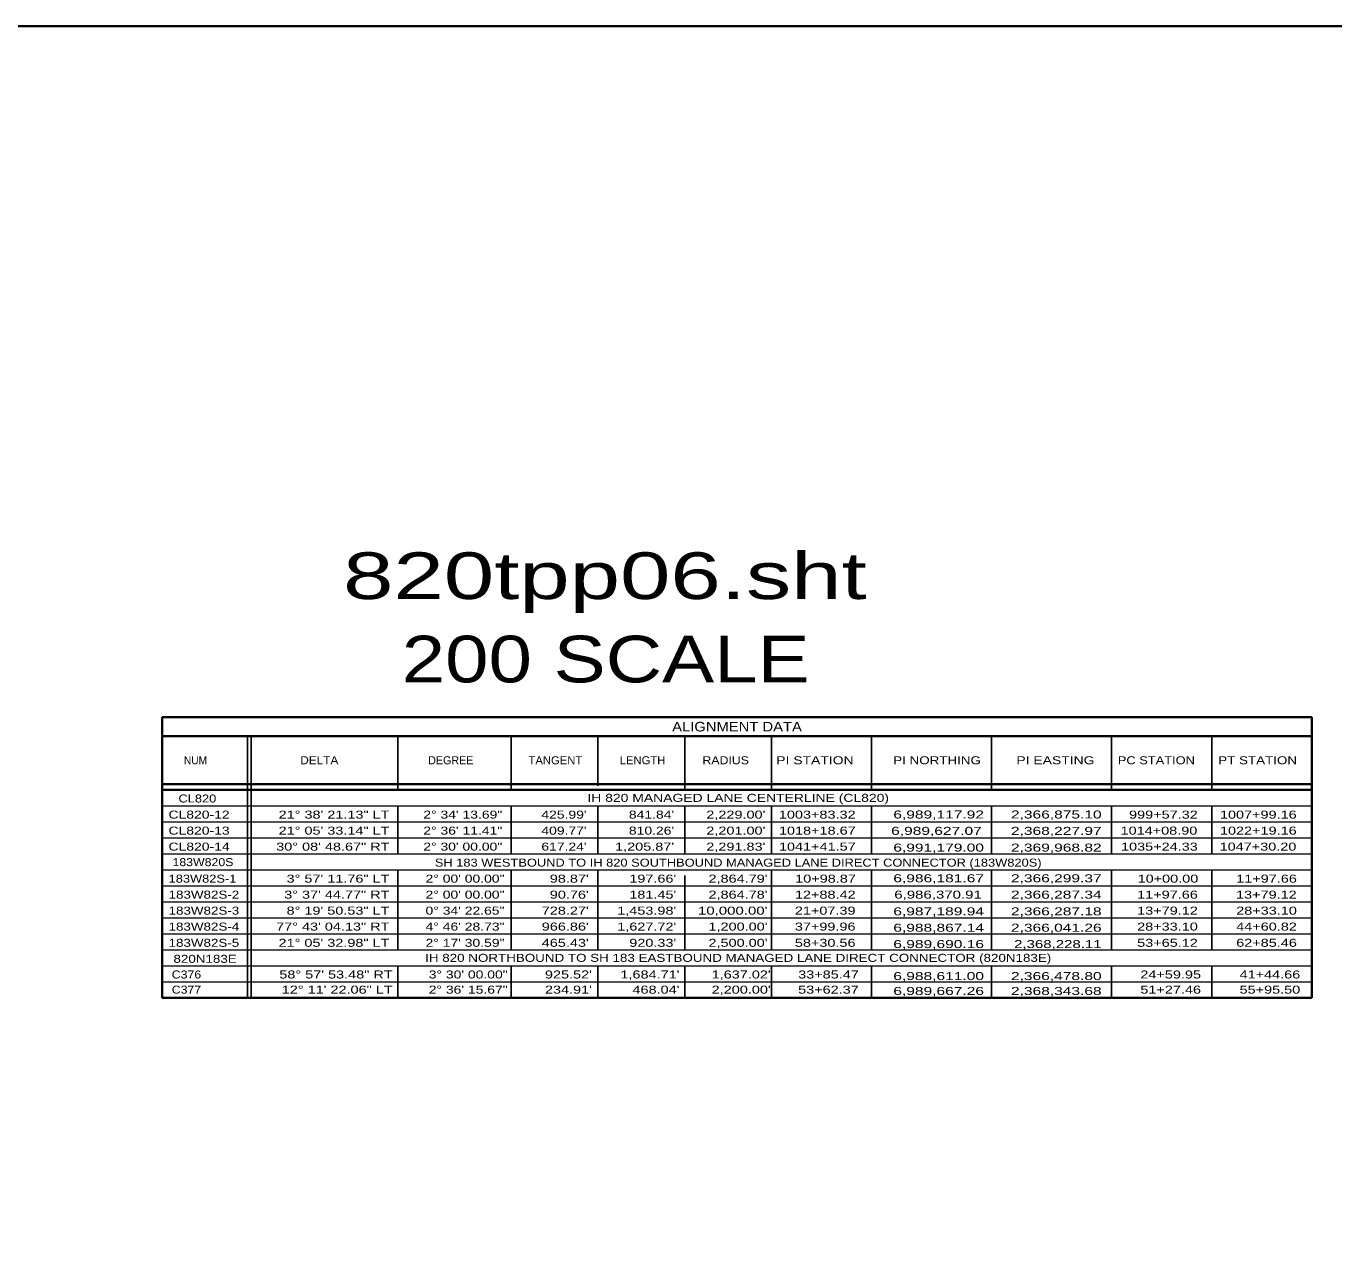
# Model space of a CAD drawing. Extents: x 1953053 to 1967065, y 7363860 to 7371201.
# Drawn here: x 1963762 to 1965722, y 7369366 to 7371201 of the extents above; entities that cross this region are included whole.
import ezdxf
from ezdxf.enums import TextEntityAlignment as Align

# ---------------------------------------------------------------- set-up
doc = ezdxf.new("R2010")
doc.units = 0
doc.header["$LTSCALE"] = 4.8
doc.layers.add('10', color=7, linetype='Continuous')
doc.layers.add('12', color=7, linetype='Continuous', lineweight=25)
doc.layers.add('62', color=7, linetype='Continuous', lineweight=35)

msp = doc.modelspace()

# ---------------------------------------------------------------- linework, layer by layer
at = {"layer": '12', "lineweight": 35}
for p, q in [((1965689.378, 7370164.879), (1963966.046, 7370164.879)), ((1963966.046, 7370164.879), (1963966.046, 7369743.746)), ((1965689.378, 7369743.746), (1965689.378, 7370164.879)), ((1963966.046, 7370136.079), (1965689.378, 7370136.079)), ((1963966.046, 7370064.079), (1965689.378, 7370064.079)), ((1963966.046, 7370055.746), (1965689.378, 7370055.746)), ((1963966.046, 7369743.746), (1965689.378, 7369743.746))]:
    msp.add_line(p, q, dxfattribs=at)
at = {"layer": '12'}
for p, q in [((1964093.891, 7370136.079), (1964093.891, 7369743.746)), ((1964099.378, 7370136.079), (1964099.378, 7369743.746)), ((1964319.378, 7370136.079), (1964319.378, 7370055.746)), ((1964489.378, 7370136.079), (1964489.378, 7370055.746)), ((1964619.378, 7370136.079), (1964619.378, 7370061.892)), ((1964749.378, 7370136.079), (1964749.378, 7370055.746)), ((1964879.378, 7370136.079), (1964879.378, 7370055.746)), ((1965029.378, 7370136.079), (1965029.378, 7370055.746)), ((1965209.378, 7370136.079), (1965209.378, 7370055.746)), ((1965389.378, 7370136.079), (1965389.378, 7370056.955)), ((1965539.378, 7370136.079), (1965539.378, 7370055.746)), ((1964093.891, 7370114.479), (1964093.891, 7369838.526)), ((1964319.378, 7370031.746), (1964319.378, 7369959.746)), ((1964489.378, 7370031.746), (1964489.378, 7369959.746)), ((1964619.378, 7370031.746), (1964619.378, 7369959.746)), ((1964749.378, 7370031.746), (1964749.378, 7369959.746)), ((1964879.378, 7370031.746), (1964879.378, 7369959.746)), ((1965029.378, 7370031.746), (1965029.378, 7369959.746)), ((1965209.378, 7370031.746), (1965209.378, 7369959.746)), ((1965389.378, 7370031.746), (1965389.378, 7369959.746)), ((1965539.378, 7370031.746), (1965539.378, 7369959.746)), ((1964319.378, 7369935.746), (1964319.378, 7369815.746)), ((1964489.378, 7369935.746), (1964489.378, 7369815.746)), ((1964619.378, 7369935.746), (1964619.378, 7369815.746)), ((1964749.378, 7369927.372), (1964749.378, 7369815.746)), ((1964879.378, 7369935.746), (1964879.378, 7369815.746)), ((1965029.378, 7369935.746), (1965029.378, 7369815.746)), ((1965209.378, 7369935.746), (1965209.378, 7369815.746)), ((1965389.378, 7369935.746), (1965389.378, 7369815.746)), ((1965539.378, 7369935.746), (1965539.378, 7369815.746)), ((1964319.378, 7369791.746), (1964319.378, 7369743.746)), ((1964489.378, 7369791.746), (1964489.378, 7369743.746)), ((1964619.378, 7369791.746), (1964619.378, 7369743.746)), ((1964749.378, 7369791.746), (1964749.378, 7369743.746)), ((1964879.378, 7369791.746), (1964879.378, 7369743.746)), ((1965029.378, 7369791.746), (1965029.378, 7369743.746)), ((1965209.378, 7369791.746), (1965209.378, 7369743.746)), ((1965389.378, 7369791.746), (1965389.378, 7369743.746)), ((1965539.378, 7369791.746), (1965539.378, 7369743.746))]:
    msp.add_line(p, q, dxfattribs=at)
at = {"layer": '12', "lineweight": 13}
for p, q in [((1963966.046, 7370031.746), (1965689.378, 7370031.746)), ((1963966.046, 7370007.746), (1965689.378, 7370007.746)), ((1963966.046, 7369983.746), (1965689.378, 7369983.746)), ((1963966.046, 7369959.746), (1965689.378, 7369959.746)), ((1963966.046, 7369935.746), (1965689.378, 7369935.746)), ((1963966.046, 7369911.746), (1965689.378, 7369911.746)), ((1963966.046, 7369887.746), (1965689.378, 7369887.746)), ((1963966.046, 7369863.746), (1965689.378, 7369863.746)), ((1963966.046, 7369839.746), (1965689.378, 7369839.746)), ((1963966.046, 7369815.746), (1965689.378, 7369815.746)), ((1963966.046, 7369791.746), (1965689.378, 7369791.746)), ((1963966.046, 7369767.746), (1965689.378, 7369767.746))]:
    msp.add_line(p, q, dxfattribs=at)
at = {"layer": '62'}
msp.add_lwpolyline([(1953052.784, 7371201.108), (1967065.314, 7371201.108), (1967065.314, 7363859.877), (1953052.784, 7363859.877)], close=True, dxfattribs=at)

# ---------------------------------------------------------------- texts
at = {"layer": '10'}
for s, width, p in [('CL820', 1.2, (1963990.551, 7370036.747)), ('CL820-12', 1.3, (1963975.667, 7370012.572)), ('CL820-13', 1.3, (1963975.667, 7369988.572)), ('CL820-14', 1.3, (1963975.667, 7369964.572)), ('183W820S', 1.15, (1963981.635, 7369941.279)), ('183W82S-1', 1.2, (1963975.75, 7369916.572)), ('183W82S-2', 1.25, (1963975.75, 7369892.572)), ('183W82S-3', 1.25, (1963975.75, 7369868.572)), ('183W82S-4', 1.25, (1963975.75, 7369844.644)), ('183W82S-5', 1.25, (1963975.75, 7369820.31)), ('820N183E', 1.25, (1963983.108, 7369796.285)), ('C376', 1.15, (1963980.523, 7369772.787)), ('C377', 1.15, (1963980.523, 7369750.075))]:
    msp.add_text(s, height=12, dxfattribs=dict(at, width=width)).set_placement(p)
for s, width, p in [('IH 820 MANAGED LANE CENTERLINE (CL820)', 1.3, (1964829.576, 7370037.713)), ('SH 183 WESTBOUND TO IH 820 SOUTHBOUND MANAGED LANE DIRECT CONNECTOR (183W820S)', 1.2, (1964829.578, 7369940.563)), ('IH 820 NORTHBOUND TO SH 183 EASTBOUND MANAGED LANE DIRECT CONNECTOR (820N183E)', 1.25, (1964829.578, 7369797.757))]:
    msp.add_text(s, height=12, dxfattribs=dict(at, width=width)).set_placement(p, align=Align.CENTER)
for s, width, p in [('21° 38\' 21.13" LT', 1.35, (1964306.9, 7370012.572)), ('2° 34\' 13.69"', 1.3, (1964475.895, 7370012.572)), ("425.99'", 1.3, (1964602.305, 7370012.572)), ("841.84'", 1.3, (1964733.502, 7370012.572)), ("2,229.00'", 1.35, (1964870.272, 7370012.572)), ('1003+83.32', 1.35, (1965005.578, 7370012.572)), ('6,989,117.92', 1.45, (1965197.965, 7370012.75)), ('2,366,875.10', 1.45, (1965374.312, 7370012.75)), ('999+57.32', 1.35, (1965518.44, 7370012.572)), ('1007+99.16', 1.35, (1965666.701, 7370012.572)), ('21° 05\' 33.14" LT', 1.35, (1964306.9, 7369988.572)), ('2° 36\' 11.41"', 1.3, (1964475.895, 7369988.572)), ("409.77'", 1.3, (1964602.305, 7369988.572)), ("810.26'", 1.3, (1964733.502, 7369988.572)), ("2,201.00'", 1.35, (1964870.272, 7369988.572)), ('1018+18.67', 1.35, (1965005.674, 7369988.572)), ('6,989,627.07', 1.45, (1965194.692, 7369988.211)), ('2,368,227.97', 1.45, (1965374.312, 7369988.211)), ('1014+08.90', 1.35, (1965517.763, 7369988.572)), ('1022+19.16', 1.35, (1965666.701, 7369988.572)), ('30° 08\' 48.67" RT', 1.35, (1964306.9, 7369964.572)), ('2° 30\' 00.00"', 1.3, (1964475.895, 7369964.572)), ("617.24'", 1.3, (1964602.305, 7369964.572)), ("1,205.87'", 1.35, (1964733.502, 7369964.572)), ("2,291.83'", 1.35, (1964870.272, 7369964.572)), ('1041+41.57', 1.35, (1965005.674, 7369964.572)), ('6,991,179.00', 1.45, (1965197.965, 7369963.127)), ('2,369,968.82', 1.45, (1965374.312, 7369963.127)), ('1035+24.33', 1.35, (1965518.438, 7369964.572)), ('1047+30.20', 1.35, (1965666.213, 7369964.572)), ('3° 57\' 11.76" LT', 1.35, (1964306.817, 7369916.572)), ('2° 00\' 00.00"', 1.3, (1964479.278, 7369916.572)), ("98.87'", 1.35, (1964605.52, 7369916.572)), ("197.66'", 1.35, (1964736.717, 7369916.572)), ("2,864.79'", 1.35, (1964873.487, 7369916.572)), ('10+98.87', 1.35, (1965005.956, 7369916.572)), ('6,986,181.67', 1.45, (1965197.965, 7369917.12)), ('2,366,299.37', 1.45, (1965374.312, 7369917.12)), ('10+00.00', 1.35, (1965519.209, 7369916.572)), ('11+97.66', 1.35, (1965666.985, 7369916.572)), ('3° 37\' 44.77" RT', 1.35, (1964306.817, 7369892.572)), ('2° 00\' 00.00"', 1.3, (1964479.278, 7369892.572)), ("90.76'", 1.35, (1964605.52, 7369892.572)), ("181.45'", 1.35, (1964736.717, 7369892.572)), ("2,864.78'", 1.35, (1964873.487, 7369892.572)), ('12+88.42', 1.35, (1965005.579, 7369892.572)), ('6,986,370.91', 1.4, (1965194.692, 7369892.581)), ('2,366,287.34', 1.45, (1965374.312, 7369892.581)), ('11+97.66', 1.35, (1965518.535, 7369892.572)), ('13+79.12', 1.35, (1965666.75, 7369892.572)), ('8° 19\' 50.53" LT', 1.35, (1964306.817, 7369868.572)), ('0° 34\' 22.65"', 1.3, (1964479.278, 7369868.572)), ("728.27'", 1.35, (1964605.52, 7369868.572)), ("1,453.98'", 1.35, (1964736.717, 7369868.572)), ("10,000.00'", 1.4, (1964873.487, 7369868.572)), ('21+07.39', 1.35, (1965005.44, 7369868.572)), ('6,987,189.94', 1.45, (1965197.965, 7369867.497)), ('2,366,287.18', 1.45, (1965374.312, 7369867.497)), ('13+79.12', 1.35, (1965518.535, 7369868.572)), ('28+33.10', 1.35, (1965666.985, 7369868.572)), ('77° 43\' 04.13" RT', 1.35, (1964306.817, 7369844.644)), ('4° 46\' 28.73"', 1.3, (1964479.278, 7369844.644)), ("966.86'", 1.35, (1964605.52, 7369844.644)), ("1,627.72'", 1.35, (1964736.717, 7369844.644)), ("1,200.00'", 1.35, (1964873.487, 7369844.644)), ('37+99.96', 1.35, (1965005.44, 7369844.644)), ('6,988,867.14', 1.45, (1965197.965, 7369842.957)), ('2,366,041.26', 1.45, (1965374.312, 7369842.957)), ('28+33.10', 1.35, (1965518.535, 7369844.644)), ('44+60.82', 1.35, (1965666.985, 7369844.644)), ('21° 05\' 32.98" LT', 1.35, (1964306.817, 7369820.31)), ('2° 17\' 30.59"', 1.3, (1964479.278, 7369820.31)), ("465.43'", 1.35, (1964605.52, 7369820.31)), ("920.33'", 1.35, (1964736.717, 7369820.31)), ("2,500.00'", 1.35, (1964873.487, 7369820.31)), ('58+30.56', 1.35, (1965005.44, 7369820.31)), ('6,989,690.16', 1.45, (1965197.965, 7369818.419)), ('2,368,228.11', 1.4, (1965374.312, 7369818.419)), ('53+65.12', 1.35, (1965518.535, 7369820.31)), ('62+85.46', 1.35, (1965666.985, 7369820.31)), ('58° 57\' 53.48" RT', 1.35, (1964311.59, 7369772.787)), ('3° 30\' 00.00"', 1.3, (1964484.051, 7369772.787)), ("925.52'", 1.35, (1964610.293, 7369772.787)), ("1,684.71'", 1.35, (1964741.49, 7369772.787)), ("1,637.02'", 1.35, (1964878.26, 7369772.787)), ('33+85.47', 1.35, (1965010.442, 7369772.787)), ('6,988,611.00', 1.45, (1965197.965, 7369770.432)), ('2,366,478.80', 1.45, (1965374.312, 7369770.432)), ('24+59.95', 1.35, (1965523.308, 7369772.787)), ('41+44.66', 1.35, (1965672.04, 7369772.787)), ('12° 11\' 22.06" LT', 1.35, (1964311.59, 7369750.075)), ('2° 36\' 15.67"', 1.3, (1964484.051, 7369750.075)), ("234.91'", 1.35, (1964610.293, 7369750.075)), ("468.04'", 1.35, (1964741.49, 7369750.075)), ("2,200.00'", 1.35, (1964878.26, 7369750.075)), ('53+62.37', 1.35, (1965010.352, 7369750.075)), ('6,989,667.26', 1.45, (1965197.965, 7369748.074)), ('2,368,343.68', 1.45, (1965374.312, 7369748.074)), ('51+27.46', 1.35, (1965523.308, 7369750.075)), ('55+95.50', 1.35, (1965672.04, 7369750.075))]:
    msp.add_text(s, height=12, dxfattribs=dict(at, width=width)).set_placement(p, align=Align.RIGHT)
at = {"layer": '12'}
for s, height, width, p in [('ALIGNMENT DATA', 14.4, 1.15, (1964827.819, 7370143.278)), ('NUM', 12, 0.95, (1964016.093, 7370094.075)), ('DELTA', 12, 1.1, (1964201.669, 7370094.078)), ('TANGENT', 12, 1.05, (1964555.566, 7370094.078)), ('LENGTH', 12, 1.05, (1964686.201, 7370094.078)), ('RADIUS', 12, 1.15, (1964810.811, 7370094.078)), ('PI STATION', 12, 1.3, (1964944.615, 7370094.078)), ('PI NORTHING', 12, 1.25, (1965127.691, 7370094.078)), ('PI EASTING', 12, 1.3, (1965305.082, 7370094.078)), ('PC STATION', 12, 1.2, (1965456.387, 7370094.078)), ('PT STATION', 12, 1.25, (1965608.158, 7370094.078))]:
    msp.add_text(s, height=height, dxfattribs=dict(at, width=width)).set_placement(p, align=Align.CENTER)
msp.add_text('DEGREE', height=12, dxfattribs=at).set_placement((1964398.755, 7370094.078), align=Align.CENTER)
at = {"layer": '62'}
for s, width, p in [('820tpp06.sht', 1.45, (1964629.802, 7370341.878)), ('200 SCALE', 1.25, (1964630.91, 7370216.878))]:
    msp.add_text(s, height=70, dxfattribs=dict(at, width=width)).set_placement(p, align=Align.CENTER)

doc.saveas('drawing.dxf')
